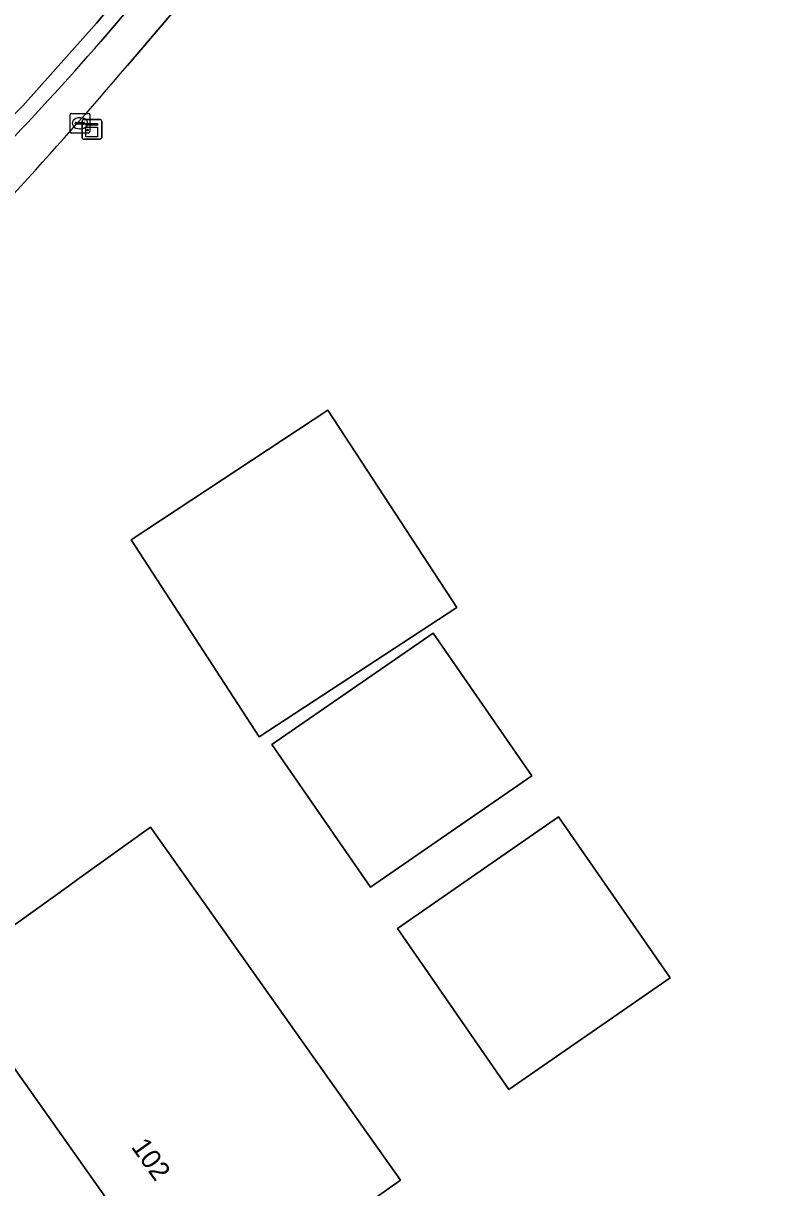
# Model space of a CAD drawing. Extents: x 152881 to 155736, y 382924 to 386919.
# Drawn here: x 152957.3 to 152996.3, y 384929.7 to 384989.2 of the extents above; entities that cross this region are included whole.
import ezdxf

# ---------------------------------------------------------------- set-up
doc = ezdxf.new("R2010")
doc.units = 0
for name, color, linetype in [('IMGEO_Erf', 7, 'Continuous'), ('IMGEO_Fietspad_gesloten', 7, 'Continuous'), ('IMGEO_Kast', 7, 'Continuous'), ('IMGEO_Pand', 7, 'Continuous'), ('IMGEO_Pand_nummerreeks', 7, 'Continuous'), ('IMGEO_Rijbaan_lokaal_gesloten', 7, 'Continuous'), ('IMGEO_Rijbaan_lokaal_open', 7, 'Continuous'), ('IMGEO_Rioolput', 7, 'Continuous')]:
    doc.layers.add(name, color=color, linetype=linetype)

msp = doc.modelspace()

# ---------------------------------------------------------------- linework, layer by layer
at = {"layer": 'IMGEO_Erf'}
msp.add_lwpolyline([(152988.959, 385018.696), (152986.373, 385015.247), (152984.091, 385012.207), (152980.28, 385007.528), (152976.884, 385003.224), (152973.907, 385000), (152971.609, 384997.512), (152968.503, 384994.102), (152965.799, 384990.83), (152962.581, 384987.025)], dxfattribs=at)
for points in [[(152972.789, 384969.44), (152979.38, 384959.37), (152969.3, 384952.76), (152962.759, 384962.82)], [(152978.166, 384958.053), (152983.201, 384950.775), (152974.977, 384945.086), (152969.942, 384952.364)], [(152984.574, 384948.67), (152990.257, 384940.455), (152982.033, 384934.766), (152976.35, 384942.98)], [(152953.361, 384940.698), (152959.564, 384945.145), (152960.092, 384945.523), (152963.755, 384948.15), (152966.642, 384944.069), (152976.5, 384930.135), (152973.431, 384927.963), (152976.891, 384923.073), (152973.602, 384920.746), (152969.52, 384917.858)]]:
    msp.add_lwpolyline(points, close=True, dxfattribs=at)
msp.add_arc((152770.156, 385151.69), 253.263, 315.47725, 319.44526, dxfattribs=at)
at = {"layer": 'IMGEO_Fietspad_gesloten'}
for points in [[(153005.558, 385043.395), (153000, 385035.959), (152993.152, 385026.798), (152990.603, 385024.147), (152990.479, 385023.995), (152988.609, 385021.619), (152987.301, 385019.884), (152984.67, 385016.466), (152982.355, 385013.461), (152978.607, 385008.801), (152975.262, 385004.599), (152971.179, 385000), (152968.595, 384997.09), (152964.984, 384992.697), (152961.215, 384988.254)], [(152962.581, 384987.025), (152965.799, 384990.83)]]:
    msp.add_lwpolyline(points, dxfattribs=at)
for centre, radius, start, end in [((152849.838, 385085.062), 147.569, 312.74109, 319.00316), ((152770.156, 385151.69), 253.263, 315.47725, 319.44526)]:
    msp.add_arc(centre, radius, start, end, dxfattribs=at)
at = {"layer": 'IMGEO_Kast'}
for p, q in [((152960.332, 384984.266), (152961.173, 384984.266)), ((152961.173, 384984.266), (152960.332, 384984.266)), ((152960.257, 384983.341), (152960.257, 384984.182)), ((152960.257, 384984.182), (152960.257, 384983.341)), ((152961.257, 384984.191), (152961.257, 384983.35)), ((152961.257, 384983.35), (152961.257, 384984.191)), ((152961.182, 384983.266), (152960.341, 384983.266)), ((152960.341, 384983.266), (152961.182, 384983.266))]:
    msp.add_line(p, q, dxfattribs=at)
for points in [[(152960.452, 384984.056), (152961.052, 384984.056), (152961.052, 384983.971), (152960.452, 384983.971), (152960.452, 384984.056)], [(152960.452, 384983.881), (152961.052, 384983.881), (152961.052, 384983.392), (152960.452, 384983.392), (152960.452, 384983.881)]]:
    msp.add_lwpolyline(points, dxfattribs=at)
msp.add_circle((152960.536, 384983.73), 0.0377, dxfattribs=at)
for centre, start, end in [((152960.335, 384984.188), 92.4484, 184.28452), ((152960.335, 384984.188), 92.4484, 184.28452), ((152961.179, 384984.188), 2.4484, 94.28452), ((152961.179, 384984.188), 2.4484, 94.28452), ((152960.335, 384983.344), 182.4484, 274.28452), ((152960.335, 384983.344), 182.4484, 274.28452), ((152961.179, 384983.344), 272.4484, 4.28452), ((152961.179, 384983.344), 272.4484, 4.28452)]:
    msp.add_arc(centre, 0.0779, start, end, dxfattribs=at)
at = {"layer": 'IMGEO_Pand'}
for points in [[(152972.789, 384969.44), (152962.759, 384962.82), (152969.3, 384952.76), (152979.38, 384959.37)], [(152974.977, 384945.086), (152983.201, 384950.775), (152978.166, 384958.053), (152969.942, 384952.364)], [(152982.033, 384934.766), (152990.257, 384940.455), (152984.574, 384948.67), (152976.35, 384942.98)], [(152953.361, 384940.698), (152969.52, 384917.858), (152973.602, 384920.746), (152976.891, 384923.073), (152973.431, 384927.963), (152976.5, 384930.135), (152966.642, 384944.069), (152963.755, 384948.15), (152960.092, 384945.523), (152959.564, 384945.145)]]:
    msp.add_lwpolyline(points, close=True, dxfattribs=at)
at = {"layer": 'IMGEO_Rijbaan_lokaal_gesloten'}
msp.add_lwpolyline([(152934.413, 384970.705), (152920.087, 384959.424), (152918.374, 384958.267), (152921.577, 384953.958), (152931.359, 384961.408), (152937.222, 384966.042), (152946.43, 384974.266), (152949.587, 384977.419), (152957.232, 384984.967), (152960.992, 384989.193), (152967.34, 384996.77), (152976.729, 385009.189), (152985.588, 385021.361), (152985.658, 385021.458), (152987.933, 385024.584), (152991.207, 385029.157), (153005.301, 385048.581), (153023.094, 385073.275)], dxfattribs=at)
at = {"layer": 'IMGEO_Rijbaan_lokaal_open'}
msp.add_lwpolyline([(152961.215, 384988.254), (152964.984, 384992.697), (152968.595, 384997.09), (152970.886, 385000), (152975.013, 385005.472), (152981.333, 385014.199), (152983.553, 385017.266), (152986.274, 385021.023), (152986.067, 385021.169), (152986.05, 385021.181), (152985.658, 385021.458), (152985.588, 385021.361), (152976.729, 385009.189), (152967.34, 384996.77), (152960.992, 384989.193), (152957.232, 384984.967), (152949.587, 384977.419), (152946.43, 384974.266), (152937.222, 384966.042), (152931.359, 384961.408), (152921.577, 384953.958), (152917.332, 384950.608)], dxfattribs=at)
msp.add_arc((152849.838, 385085.062), 147.569, 312.74109, 319.00316, dxfattribs=at)
at = {"layer": 'IMGEO_Rioolput'}
for p, q in [((152959.648, 384983.649), (152959.648, 384984.501)), ((152959.723, 384984.575), (152960.575, 384984.575)), ((152960.136, 384984.355), (152960.161, 384984.355)), ((152960.649, 384984.501), (152960.649, 384983.649)), ((152959.907, 384984.069), (152959.907, 384984.081)), ((152960.345, 384984.032), (152959.947, 384984.032)), ((152959.95, 384984.118), (152960.348, 384984.118)), ((152960.159, 384983.795), (152960.134, 384983.795)), ((152960.391, 384984.081), (152960.391, 384984.069)), ((152960.575, 384983.575), (152959.723, 384983.575))]:
    msp.add_line(p, q, dxfattribs=at)
for points in [[(152959.648, 384983.649), (152959.648, 384984.501)], [(152959.723, 384984.575), (152960.575, 384984.575)], [(152960.649, 384984.501), (152960.649, 384983.649)], [(152960.575, 384983.575), (152959.723, 384983.575)]]:
    msp.add_lwpolyline(points, dxfattribs=at)
for centre, radius, start, end in [((152959.725, 384984.499), 0.0765, 91.55205, 178.44795), ((152959.725, 384984.499), 0.0765, 91.55205, 178.44795), ((152960.573, 384984.499), 0.0765, 1.55205, 88.44795), ((152960.573, 384984.499), 0.0765, 1.55205, 88.44795), ((152959.725, 384983.651), 0.0765, 181.55205, 268.44795), ((152959.725, 384983.651), 0.0765, 181.55205, 268.44795), ((152959.947, 384984.078), 0.0403, 85.87752, 175.75265), ((152959.944, 384984.068), 0.0366, 178.93798, 274.71019), ((152960.348, 384984.075), 0.043, 264.86636, 352.45326), ((152960.352, 384984.08), 0.0386, 1.73085, 96.63898), ((152960.573, 384983.651), 0.0765, 271.55205, 358.44795), ((152960.573, 384983.651), 0.0765, 271.55205, 358.44795)]:
    msp.add_arc(centre, radius, start, end, dxfattribs=at)
for centre, major_axis, ratio, start_param, end_param in [((152960.135, 384984.075), (-0.387, 0.002), 0.722429, 4.712389, 7.853982), ((152960.16, 384984.075), (-0.39, 0.002), 0.717154, 1.570796, 4.712389)]:
    msp.add_ellipse(centre, major_axis=major_axis, ratio=ratio, start_param=start_param, end_param=end_param, dxfattribs=at)

# ---------------------------------------------------------------- texts
at = {"layer": 'IMGEO_Pand_nummerreeks'}
msp.add_text('102', height=1, rotation=305.31118, dxfattribs=at).set_placement((152962.726, 384931.835))

doc.saveas('drawing.dxf')
